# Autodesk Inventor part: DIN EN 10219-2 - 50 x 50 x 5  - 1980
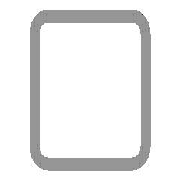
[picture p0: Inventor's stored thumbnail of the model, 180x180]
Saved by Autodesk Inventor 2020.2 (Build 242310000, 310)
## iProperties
Created: 2019-01
Part Number: DIN EN 10219-2 - 50 x 50 x 5  - 1980
Material: Stahl, weich
Description: Kaltgeformte, geschweißte Baustahl-Hohlprofile aus unlegiertem Feinkorn-Baustahl
Document SubType Name: Modeling
Standard: DIN
Designer: lutzd
Standard Revision: 2006-07
Standards Organization: DIN
Language: de-DE
Size Designation: 50 x 50 x 5
Categories: <MemberInstance><Categories><Category DisplayName="Profile" InternalName="089c4875-fa83-4c05-b084-43b9cc11f5ed" Mnemonic="GRDR"><CategoryParameter DisplayName="
Stock Number: 50 x 50 x 5
Mass: 12983.8 g
Surface Area: 6637.87 cm^2
Volume: 1653.99 cm^3
Density: 7.85 g/cm^3
Appearance: Semi-Polished(8)
IsCustomPart: 1
_CCFamilyMember: 16
_CCFamilyDisplayName: DIN EN 10219-2 (Quadratisches Hohlprofil - Kaltgeformt) - Kaltgeformte, geschweißte Baustahl-Hohlprofile aus unlegiertem Feinkorn-Baustahl
_FrameMemberDoc: Frame Member File
_Version: 15.0.0
_GetPNFromCC: 1
G_L: 1980,000 mm
G_W: 50,000 mm
G_H: 50,000 mm
DocNumber: ADSK-014377
Folder: .
Mass: 12,984 kg
VLT_Material: Stahl, weich
+242677BD-47D0-4A52-B799-A88C75D94CB7+SCHNITTDETAIL1: Schnittwinkel 90,00 grd
+CBB98EEB-DE4D-4857-9D50-4EAEC970D9ED+SCHNITTDETAIL2: Schnittwinkel 90,00 grd
Dimensions: 50x50x1980 mm
Title: Profil-Bauteil
Author: lutzd
Revision Number: -
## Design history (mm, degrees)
node "Startebene"
node "Endebene"
sketch "Skizze"
  geometry: L1 (-25, -15)-(-25, 15); L2 (-15, 25)-(15, 25); L3 (25, 15)-(25, -15); L4 (15, -25)-(-15, -25); L5 (-15, 20)-(15, 20); L6 (20, 15)-(20, -15); L7 (15, -20)-(-15, -20); L8 (-20, -15)-(-20, 15); L9 (0, 37.899)-(0, -37.899) reference; L10 (-37.899, 0)-(37.899, 0) reference; A1 r 10 centre (-15, -15) between (-25, -15) and (-15, -25); A2 r 10 centre (-15, 15) between (-15, 25) and (-25, 15); A3 r 10 centre (15, 15) between (25, 15) and (15, 25); A4 r 10 centre (15, -15) between (15, -25) and (25, -15); A5 r 5 centre (-15, 15) between (-15, 20) and (-20, 15); A6 r 5 centre (15, 15) between (20, 15) and (15, 20); A7 r 5 centre (15, -15) between (15, -20) and (20, -15); A8 r 5 centre (-15, -15) between (-20, -15) and (-15, -20)
  constraints: 16 end point, 16 point on circle, 8 centre point, 8 tangent, 4 parallel, 3 equal radius, 2 perpendicular, 7 other
  dimensions: "d7" = 10 radius of A1 (= G_IR); "d10" = 50 distance between parallel lines of L2 L4 (= G_H); "d11" = 50 distance between parallel lines of L1 L3 (= G_W); "d12" = 5 distance between parallel lines of L3 L6 (= G_T); "d15" = 25 distance between parallel lines of L2 L10 (= 0.5 x d10); "d16" = 25 distance between parallel lines of L9 L3 (= 0.5 x d11)
extrude "Körper" new body sketch "Skizze" stored distance "d3" = 1980 (= G_L); taper "d4" = 0 deg
node "Driven Length"
  sketch "Sketch3"
    geometry: L1 (0, 0)-(10, 0) reference
    constraints: 2 end point, 1 horizontal
  workplane "Work Plane3"
  sketch "Sketch4"
    geometry: L1 (-2, 50)-(12, 50) reference; L2 (-2, 2030)-(12, 2030) reference
    dimensions: "d18" = 1980 distance between parallel lines of L1 L2 (derived)
workplane "Arbeitsebene4"
feature "Trennen1"
workplane "Arbeitsebene5"
feature "Trennen2"
sketch "Skizze5"
  geometry: L1 (1980, -30)-(1980, 0) reference; L2 (0, -30)-(0, 0) reference; 13 further points
  constraints: 5 midpoint, 12 other
  dimensions: "d20" = 200 distance of point (390, -15) point (190, -15); "d21" = 200 distance of point (590, -15) point (390, -15) (= d20); "d22" = 200 distance of point (790, -15) point (590, -15) (= d20); "d23" = 200 distance of point (990, -15) point (790, -15) (= d20); "d24" = 200 distance of point (990, -15) point (1190, -15) (= d20); "d25" = 200 distance of point (1390, -15) point (1190, -15) (= d20); "d26" = 200 distance of point (1590, -15) point (1390, -15) (= d20); "d27" = 200 distance of point (1590, -15) point (1790, -15) (= d20)
hole "Bohrung1" sketch "Skizze5" at (190, -15), (390, -15), (590, -15), (790, -15), (1190, -15), (1390, -15), (1590, -15), (1790, -15) diameter "d30" = 4.134; stored, may be unused: countersink angle "d34" = 90 deg, drill point angle "d36" = 118 deg; dims "d31" = 10, "d32" = 10.4, "d33" = 2, "d35" = 14.2
workplane "Arbeitsebene6"
body "Solid1"
other parameters: "G_W" = 50 [user parameter; used in 1 equation term], "G_H" = 50 [user parameter; used in 1 equation term], "G_T" = 5 [user parameter; used in 1 equation term], "G_IR" = 10 [user parameter; used in 1 equation term], "G_L" = 1980 (= d18) [user parameter; used in 1 equation term], "d17" = 90 deg
